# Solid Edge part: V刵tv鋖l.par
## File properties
Author: Türk
Template: Iso Part.par
Last saved by: Türk
Revision: 24
Application: Solid Edge
Accuracy: 0,990
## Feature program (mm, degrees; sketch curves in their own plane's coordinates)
pattern "PatternOccurrence_1"  XOffset = 16.3636 deg
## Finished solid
Body 1: solid body, 412 faces, 1056 edges, 656 vertices.
  Faces by surface: cylinder 173, plane 149, torus 80, blend 10
  Edges by curve: line 510, circle 346, intersection 180, ellipse 20
Bounding box of the edges (mm; curved faces can reach further): 165.000 x 806.000 x 165.000, from (-82.5, -548, -82.5) to (82.5, 258, 82.5).
Cylindrical faces by radius (mm): R1 x80, R5 x20, R15 x27, R17.5 x10, R20 x6, R45 x20, R82.5 x10
Toroidal faces (ring radius, tube radius in mm): R4 r1 x20, R46 r1 x40, R77.5 r5 x10, R81.5 r1 x10
Planar faces by outward normal: +x 2, +y 16, +z 1, -x 2, -y 17, -z 1, oblique 110
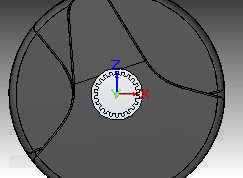
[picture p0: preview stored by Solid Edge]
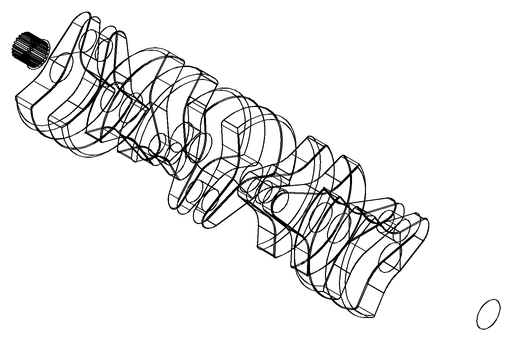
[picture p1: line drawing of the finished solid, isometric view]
